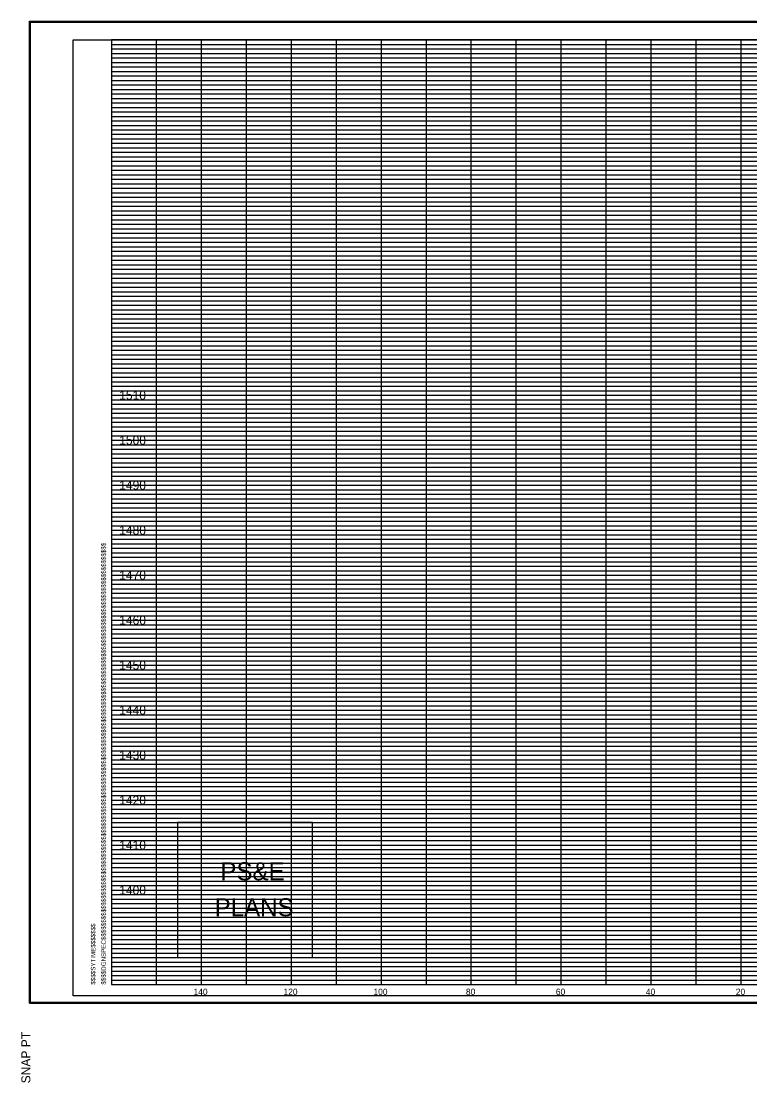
# Model space of a CAD drawing. Extents: x 980 to 2064, y 978 to 2267.
# Drawn here: x 1349.9 to 1511.9, y 1758.2 to 1994.1 of the extents above; entities that cross this region are included whole.
import ezdxf

# ---------------------------------------------------------------- set-up
doc = ezdxf.new("R2010")
doc.units = 0
for name, color, linetype in [('Default', 7, 'Continuous'), ('DESIGN - SHEET - Corner Text', 7, 'Continuous'), ('DESIGN - SHEET - Light Grid', 7, 'Continuous'), ('DESIGN - SHEET - Linework', 7, 'Continuous'), ('DESIGN - SHEET - Plot Shape', 7, 'Continuous')]:
    doc.layers.add(name, color=color, linetype=linetype)

# ---------------------------------------------------------------- blocks, each defined once
blk = doc.blocks.new('XSTSHT')
at = {"layer": 'DESIGN - SHEET - Light Grid'}
for p, q in [((0, 20.9), (8, 20.9)), ((0, 20.8), (8, 20.8)), ((8, 20.9), (16, 20.9)), ((8, 20.8), (16, 20.8)), ((0, 20.7), (8, 20.7)), ((0, 20.6), (8, 20.6)), ((8, 20.7), (16, 20.7)), ((8, 20.6), (16, 20.6)), ((0, 20.5), (8, 20.5)), ((0, 20.4), (8, 20.4)), ((0, 20.3), (8, 20.3)), ((8, 20.5), (16, 20.5)), ((8, 20.4), (16, 20.4)), ((8, 20.3), (16, 20.3)), ((0, 20.2), (8, 20.2)), ((0, 20.1), (8, 20.1)), ((8, 20.2), (16, 20.2)), ((8, 20.1), (16, 20.1)), ((0, 19.9), (8, 19.9)), ((8, 19.9), (16, 19.9)), ((0, 19.8), (8, 19.8)), ((0, 19.7), (8, 19.7)), ((0, 19.6), (8, 19.6)), ((8, 19.8), (16, 19.8)), ((8, 19.7), (16, 19.7)), ((8, 19.6), (16, 19.6)), ((0, 19.5), (8, 19.5)), ((0, 19.4), (8, 19.4)), ((8, 19.5), (16, 19.5)), ((8, 19.4), (16, 19.4)), ((0, 19.3), (8, 19.3)), ((0, 19.2), (8, 19.2)), ((8, 19.3), (16, 19.3)), ((8, 19.2), (16, 19.2)), ((0, 19.1), (8, 19.1)), ((0, 18.9), (8, 18.9)), ((8, 19.1), (16, 19.1)), ((8, 18.9), (16, 18.9)), ((0, 18.8), (8, 18.8)), ((0, 18.7), (8, 18.7)), ((8, 18.8), (16, 18.8)), ((8, 18.7), (16, 18.7)), ((0, 18.6), (8, 18.6)), ((0, 18.5), (8, 18.5)), ((8, 18.6), (16, 18.6)), ((8, 18.5), (16, 18.5)), ((0, 18.4), (8, 18.4)), ((0, 18.3), (8, 18.3)), ((0, 18.2), (8, 18.2)), ((8, 18.4), (16, 18.4)), ((8, 18.3), (16, 18.3)), ((8, 18.2), (16, 18.2)), ((0, 18.1), (8, 18.1)), ((8, 18.1), (16, 18.1)), ((0, 17.9), (8, 17.9)), ((0, 17.8), (8, 17.8)), ((0, 17.7), (8, 17.7)), ((8, 17.9), (16, 17.9)), ((8, 17.8), (16, 17.8)), ((8, 17.7), (16, 17.7)), ((0, 17.6), (8, 17.6)), ((0, 17.5), (8, 17.5)), ((8, 17.6), (16, 17.6)), ((8, 17.5), (16, 17.5)), ((0, 17.4), (8, 17.4)), ((0, 17.3), (8, 17.3)), ((8, 17.4), (16, 17.4)), ((8, 17.3), (16, 17.3)), ((0, 17.2), (8, 17.2)), ((0, 17.1), (8, 17.1)), ((8, 17.2), (16, 17.2)), ((8, 17.1), (16, 17.1)), ((0, 16.9), (8, 16.9)), ((0, 16.8), (8, 16.8)), ((8, 16.9), (16, 16.9)), ((8, 16.8), (16, 16.8)), ((0, 16.7), (8, 16.7)), ((0, 16.6), (8, 16.6)), ((8, 16.7), (16, 16.7)), ((8, 16.6), (16, 16.6)), ((0, 16.5), (8, 16.5)), ((0, 16.4), (8, 16.4)), ((0, 16.3), (8, 16.3)), ((8, 16.5), (16, 16.5)), ((8, 16.4), (16, 16.4)), ((8, 16.3), (16, 16.3)), ((0, 16.2), (8, 16.2)), ((0, 16.1), (8, 16.1)), ((8, 16.2), (16, 16.2)), ((8, 16.1), (16, 16.1)), ((0, 15.9), (8, 15.9)), ((8, 15.9), (16, 15.9)), ((0, 15.8), (8, 15.8)), ((0, 15.7), (8, 15.7)), ((0, 15.6), (8, 15.6)), ((8, 15.8), (16, 15.8)), ((8, 15.7), (16, 15.7)), ((8, 15.6), (16, 15.6)), ((0, 15.5), (8, 15.5)), ((0, 15.4), (8, 15.4)), ((8, 15.5), (16, 15.5)), ((8, 15.4), (16, 15.4)), ((0, 15.3), (8, 15.3)), ((0, 15.2), (8, 15.2)), ((8, 15.3), (16, 15.3)), ((8, 15.2), (16, 15.2)), ((0, 15.1), (8, 15.1)), ((0, 14.9), (8, 14.9)), ((8, 15.1), (16, 15.1)), ((8, 14.9), (16, 14.9)), ((0, 14.8), (8, 14.8)), ((0, 14.7), (8, 14.7)), ((8, 14.8), (16, 14.8)), ((8, 14.7), (16, 14.7)), ((0, 14.6), (8, 14.6)), ((0, 14.5), (8, 14.5)), ((0, 14.4), (8, 14.4)), ((8, 14.6), (16, 14.6)), ((8, 14.5), (16, 14.5)), ((8, 14.4), (16, 14.4)), ((0, 14.3), (8, 14.3)), ((0, 14.2), (8, 14.2)), ((8, 14.3), (16, 14.3)), ((8, 14.2), (16, 14.2)), ((0, 14.1), (8, 14.1)), ((8, 14.1), (16, 14.1)), ((0, 13.9), (8, 13.9)), ((0, 13.8), (8, 13.8)), ((0, 13.7), (8, 13.7)), ((8, 13.9), (16, 13.9)), ((8, 13.8), (16, 13.8)), ((8, 13.7), (16, 13.7)), ((0, 13.6), (8, 13.6)), ((0, 13.5), (8, 13.5)), ((8, 13.6), (16, 13.6)), ((8, 13.5), (16, 13.5)), ((0, 13.4), (8, 13.4)), ((0, 13.3), (8, 13.3)), ((8, 13.4), (16, 13.4)), ((8, 13.3), (16, 13.3)), ((0, 13.2), (8, 13.2)), ((0, 13.1), (8, 13.1)), ((8, 13.2), (16, 13.2)), ((8, 13.1), (16, 13.1)), ((0, 12.9), (8, 12.9)), ((0, 12.8), (8, 12.8)), ((8, 12.9), (16, 12.9)), ((8, 12.8), (16, 12.8)), ((0, 12.7), (8, 12.7)), ((0, 12.6), (8, 12.6)), ((8, 12.7), (16, 12.7)), ((8, 12.6), (16, 12.6)), ((0, 12.5), (8, 12.5)), ((0, 12.4), (8, 12.4)), ((0, 12.3), (8, 12.3)), ((8, 12.5), (16, 12.5)), ((8, 12.4), (16, 12.4)), ((8, 12.3), (16, 12.3)), ((0, 12.2), (8, 12.2)), ((0, 12.1), (8, 12.1)), ((8, 12.2), (16, 12.2)), ((8, 12.1), (16, 12.1)), ((0, 11.9), (8, 11.9)), ((0, 11.8), (8, 11.8)), ((8, 11.9), (16, 11.9)), ((8, 11.8), (16, 11.8)), ((0, 11.7), (8, 11.7)), ((0, 11.6), (8, 11.6)), ((8, 11.7), (16, 11.7)), ((8, 11.6), (16, 11.6)), ((0, 11.5), (8, 11.5)), ((0, 11.4), (8, 11.4)), ((8, 11.5), (16, 11.5)), ((8, 11.4), (16, 11.4)), ((0, 11.3), (8, 11.3)), ((0, 11.2), (8, 11.2)), ((0, 11.1), (8, 11.1)), ((8, 11.3), (16, 11.3)), ((8, 11.2), (16, 11.2)), ((8, 11.1), (16, 11.1)), ((0, 10.9), (8, 10.9)), ((8, 10.9), (16, 10.9)), ((0, 10.8), (8, 10.8)), ((0, 10.7), (8, 10.7)), ((8, 10.8), (16, 10.8)), ((8, 10.7), (16, 10.7)), ((0, 10.6), (8, 10.6)), ((0, 10.5), (8, 10.5)), ((0, 10.4), (8, 10.4)), ((8, 10.6), (16, 10.6)), ((8, 10.5), (16, 10.5)), ((8, 10.4), (16, 10.4)), ((0, 10.3), (8, 10.3)), ((0, 10.2), (8, 10.2)), ((8, 10.3), (16, 10.3)), ((8, 10.2), (16, 10.2)), ((0, 10.1), (8, 10.1)), ((8, 10.1), (16, 10.1)), ((0, 9.9), (8, 9.9)), ((0, 9.8), (8, 9.8)), ((0, 9.7), (8, 9.7)), ((8, 9.9), (16, 9.9)), ((8, 9.8), (16, 9.8)), ((8, 9.7), (16, 9.7)), ((0, 9.6), (8, 9.6)), ((0, 9.5), (8, 9.5)), ((8, 9.6), (16, 9.6)), ((8, 9.5), (16, 9.5)), ((0, 9.4), (8, 9.4)), ((0, 9.3), (8, 9.3)), ((8, 9.4), (16, 9.4)), ((8, 9.3), (16, 9.3)), ((0, 9.2), (8, 9.2)), ((0, 9.1), (8, 9.1)), ((8, 9.2), (16, 9.2)), ((8, 9.1), (16, 9.1)), ((0, 8.9), (8, 8.9)), ((0, 8.8), (8, 8.8)), ((8, 8.9), (16, 8.9)), ((8, 8.8), (16, 8.8)), ((0, 8.7), (8, 8.7)), ((0, 8.6), (8, 8.6)), ((0, 8.5), (8, 8.5)), ((8, 8.7), (16, 8.7)), ((8, 8.6), (16, 8.6)), ((8, 8.5), (16, 8.5)), ((0, 8.4), (8, 8.4)), ((0, 8.3), (8, 8.3)), ((8, 8.4), (16, 8.4)), ((8, 8.3), (16, 8.3)), ((0, 8.2), (8, 8.2)), ((0, 8.1), (8, 8.1)), ((8, 8.2), (16, 8.2)), ((8, 8.1), (16, 8.1)), ((0, 7.9), (8, 7.9)), ((0, 7.8), (8, 7.8)), ((8, 7.9), (16, 7.9)), ((8, 7.8), (16, 7.8)), ((0, 7.7), (8, 7.7)), ((0, 7.6), (8, 7.6)), ((8, 7.7), (16, 7.7)), ((8, 7.6), (16, 7.6)), ((0, 7.5), (8, 7.5)), ((0, 7.4), (8, 7.4)), ((8, 7.5), (16, 7.5)), ((8, 7.4), (16, 7.4)), ((0, 7.3), (8, 7.3)), ((0, 7.2), (8, 7.2)), ((0, 7.1), (8, 7.1)), ((8, 7.3), (16, 7.3)), ((8, 7.2), (16, 7.2)), ((8, 7.1), (16, 7.1)), ((0, 6.9), (8, 6.9)), ((8, 6.9), (16, 6.9)), ((0, 6.8), (8, 6.8)), ((0, 6.7), (8, 6.7)), ((8, 6.8), (16, 6.8)), ((8, 6.7), (16, 6.7)), ((0, 6.6), (8, 6.6)), ((0, 6.5), (8, 6.5)), ((0, 6.4), (8, 6.4)), ((8, 6.6), (16, 6.6)), ((8, 6.5), (16, 6.5)), ((8, 6.4), (16, 6.4)), ((0, 6.3), (8, 6.3)), ((0, 6.2), (8, 6.2)), ((8, 6.3), (16, 6.3)), ((8, 6.2), (16, 6.2)), ((0, 6.1), (8, 6.1)), ((0, 5.9), (8, 5.9)), ((8, 6.1), (16, 6.1)), ((8, 5.9), (16, 5.9)), ((0, 5.8), (8, 5.8)), ((0, 5.7), (8, 5.7)), ((8, 5.8), (16, 5.8)), ((8, 5.7), (16, 5.7)), ((0, 5.6), (8, 5.6)), ((0, 5.5), (8, 5.5)), ((8, 5.6), (16, 5.6)), ((8, 5.5), (16, 5.5)), ((0, 5.4), (8, 5.4)), ((0, 5.3), (8, 5.3)), ((0, 5.2), (8, 5.2)), ((8, 5.4), (16, 5.4)), ((8, 5.3), (16, 5.3)), ((8, 5.2), (16, 5.2)), ((0, 5.1), (8, 5.1)), ((8, 5.1), (16, 5.1)), ((0, 4.9), (8, 4.9)), ((0, 4.8), (8, 4.8)), ((8, 4.9), (16, 4.9)), ((8, 4.8), (16, 4.8)), ((0, 4.7), (8, 4.7)), ((0, 4.6), (8, 4.6)), ((0, 4.5), (8, 4.5)), ((8, 4.7), (16, 4.7)), ((8, 4.6), (16, 4.6)), ((8, 4.5), (16, 4.5)), ((0, 4.4), (8, 4.4)), ((0, 4.3), (8, 4.3)), ((8, 4.4), (16, 4.4)), ((8, 4.3), (16, 4.3)), ((0, 4.2), (8, 4.2)), ((0, 4.1), (8, 4.1)), ((8, 4.2), (16, 4.2)), ((8, 4.1), (16, 4.1)), ((0, 3.9), (8, 3.9)), ((0, 3.8), (8, 3.8)), ((8, 3.9), (16, 3.9)), ((8, 3.8), (16, 3.8)), ((0, 3.7), (8, 3.7)), ((0, 3.6), (8, 3.6)), ((8, 3.7), (16, 3.7)), ((8, 3.6), (16, 3.6)), ((0, 3.5), (8, 3.5)), ((0, 3.4), (8, 3.4)), ((8, 3.5), (16, 3.5)), ((8, 3.4), (16, 3.4)), ((0, 3.3), (8, 3.3)), ((0, 3.2), (8, 3.2)), ((0, 3.1), (8, 3.1)), ((8, 3.3), (16, 3.3)), ((8, 3.2), (16, 3.2)), ((8, 3.1), (16, 3.1)), ((0, 2.9), (8, 2.9)), ((8, 2.9), (16, 2.9)), ((0, 2.8), (8, 2.8)), ((0, 2.7), (8, 2.7)), ((0, 2.6), (8, 2.6)), ((8, 2.8), (16, 2.8)), ((8, 2.7), (16, 2.7)), ((8, 2.6), (16, 2.6)), ((0, 2.5), (8, 2.5)), ((0, 2.4), (8, 2.4)), ((8, 2.5), (16, 2.5)), ((8, 2.4), (16, 2.4)), ((0, 2.3), (8, 2.3)), ((0, 2.2), (8, 2.2)), ((8, 2.3), (16, 2.3)), ((8, 2.2), (16, 2.2)), ((0, 2.1), (8, 2.1)), ((0, 1.9), (8, 1.9)), ((8, 2.1), (16, 2.1)), ((8, 1.9), (16, 1.9)), ((0, 1.8), (8, 1.8)), ((0, 1.7), (8, 1.7)), ((8, 1.8), (16, 1.8)), ((8, 1.7), (16, 1.7)), ((0, 1.6), (8, 1.6)), ((0, 1.5), (8, 1.5)), ((8, 1.6), (16, 1.6)), ((8, 1.5), (16, 1.5)), ((0, 1.4), (8, 1.4)), ((0, 1.3), (8, 1.3)), ((0, 1.2), (8, 1.2)), ((8, 1.4), (16, 1.4)), ((8, 1.3), (16, 1.3)), ((8, 1.2), (16, 1.2)), ((0, 1.1), (8, 1.1)), ((8, 1.1), (16, 1.1)), ((0, 0.9), (8, 0.9)), ((0, 0.8), (8, 0.8)), ((8, 0.9), (16, 0.9)), ((8, 0.8), (16, 0.8)), ((0, 0.7), (8, 0.7)), ((0, 0.6), (8, 0.6)), ((0, 0.5), (8, 0.5)), ((8, 0.7), (16, 0.7)), ((8, 0.6), (16, 0.6)), ((8, 0.5), (16, 0.5)), ((0, 0.4), (8, 0.4)), ((0, 0.3), (8, 0.3)), ((8, 0.4), (16, 0.4)), ((8, 0.3), (16, 0.3)), ((0, 0.2), (8, 0.2)), ((0, 0.1), (8, 0.1)), ((8, 0.2), (16, 0.2)), ((8, 0.1), (16, 0.1))]:
    blk.add_line(p, q, dxfattribs=at)
at = {"layer": 'DESIGN - SHEET - Linework'}
for p, q in [((-1.823, -0.414), (-1.823, 21.414)), ((-1.823, 21.414), (32.217, 21.414)), ((1, 0), (1, 21)), ((2, 0), (2, 21)), ((3, 0), (3, 21)), ((4, 0), (4, 21)), ((5, 0), (5, 21)), ((6, 0), (6, 21)), ((7, 0), (7, 21)), ((8, 0), (8, 21)), ((9, 0), (9, 21)), ((10, 0), (10, 21)), ((11, 0), (11, 21)), ((12, 0), (12, 21)), ((13, 0), (13, 21)), ((14, 0), (14, 21)), ((0, 20), (28, 20)), ((0, 19), (32, 19)), ((0, 18), (32, 18)), ((0, 17), (32, 17)), ((0, 16), (32, 16)), ((0, 15), (32, 15)), ((0, 14), (32, 14)), ((0, 13), (32, 13)), ((0, 12), (32, 12)), ((0, 11), (32, 11)), ((0, 10), (32, 10)), ((0, 9), (32, 9)), ((0, 8), (32, 8)), ((0, 7), (32, 7)), ((0, 6), (32, 6)), ((0, 5), (32, 5)), ((0, 4), (32, 4)), ((0, 3), (32, 3)), ((0, 2), (32, 2)), ((0, 1), (32, 1)), ((-1.823, -0.414), (32.217, -0.414))]:
    blk.add_line(p, q, dxfattribs=at)
blk.add_lwpolyline([(0, 21), (0, 0), (32, 0), (32, 21), (0, 21)], dxfattribs=at)
at = {"layer": 'DESIGN - SHEET - Plot Shape'}
for points in [[(-1.803, 21.394), (32.197, 21.394), (32.197, -0.394), (-1.803, -0.394)], [(-0.85, 21), (32, 21), (32, -0.25), (-0.85, -0.25)]]:
    blk.add_lwpolyline(points, close=True, dxfattribs=at)
at = {"layer": 'DESIGN - SHEET - Corner Text'}
for s, height, p in [('$$$$DGNSPEC$$$$$$$$$$$$$$$$$$$$$$$$$$$$$$$$$$$$$$$$$$$$$$$$$$$$$$$$$$$$$$$$$$$$$$$$$$$$$$$$$$$$$$$$$$$$$$$$$$$$$$$$$$$$$$$$$$$', 0.100002, (-0.126, 0)), ('$$$$SYTIME$$$$$$$', 0.1, (-0.358, 0)), ('SNAP PT  ', 0.2, (-1.803, -2.194))]:
    blk.add_text(s, height=height, rotation=90, dxfattribs=at).set_placement(p)

msp = doc.modelspace()

# ---------------------------------------------------------------- linework, layer by layer
at = {"layer": 'DESIGN - SHEET - Corner Text'}
msp.add_lwpolyline([(1384.7, 1816.01), (1384.7, 1786.01), (1414.7, 1786.01), (1414.7, 1816.01)], close=True, dxfattribs=at)

# ---------------------------------------------------------------- block references
at = {"layer": 'Default', "xscale": 10, "yscale": 10}
msp.add_blockref('XSTSHT', (1370, 1780), dxfattribs=at)

# ---------------------------------------------------------------- texts
at = {"layer": 'Default'}
for s, height, p in [('     1510     ', 2, (1368.01, 1910)), ('     1500     ', 2, (1368.01, 1900)), ('     1490     ', 2, (1368.01, 1890)), ('     1480     ', 2, (1368.01, 1880)), ('     1470     ', 2, (1368.01, 1870)), ('     1460     ', 2, (1368.01, 1860)), ('     1450     ', 2, (1368.01, 1850)), ('     1440     ', 2, (1368.01, 1840)), ('     1430     ', 2, (1368.01, 1830)), ('     1420     ', 2, (1368.01, 1820)), ('     1410     ', 2, (1368.01, 1810)), ('     1400     ', 2, (1368.01, 1800)), ('     140     ', 1.4, (1385.65, 1777.7)), ('     120     ', 1.4, (1405.65, 1777.7)), ('     100     ', 1.4, (1425.65, 1777.7)), ('     80     ', 1.4, (1446.2, 1777.7)), ('     60     ', 1.4, (1466.2, 1777.7)), ('     40     ', 1.4, (1486.2, 1777.7)), ('     20     ', 1.4, (1506.2, 1777.7))]:
    msp.add_text(s, height=height, dxfattribs=at).set_placement(p)
at = {"layer": 'DESIGN - SHEET - Corner Text'}
for s, p in [('PS&E', (1394.22, 1803.19)), ('PLANS', (1392.94, 1795.19))]:
    msp.add_text(s, height=4, dxfattribs=at).set_placement(p)

doc.saveas('drawing.dxf')
